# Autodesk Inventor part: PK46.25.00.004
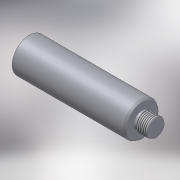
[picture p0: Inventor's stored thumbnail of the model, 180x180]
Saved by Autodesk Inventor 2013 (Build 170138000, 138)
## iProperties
Created: 2005-05
Part Number: PK46.25.00.004
Material: Steel, Mild
Document SubType Name: Modeling
Designer: PVitaliy
Manufacturer: Standard
Standards Organization: Custom
Density: 7.86 g/cm^3
Author: PVitaliy
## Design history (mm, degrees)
sketch "Эскиз2"
  geometry: L1 (0, 0)-(95.139, 0); L2 (0, 0)-(0, 25.897); L3 (0, 25.897)-(13, 35); L4 (13, 35)-(15, 35); L5 (15, 35)-(15, 50); L6 (15, 50)-(339, 50); L7 (339, 50)-(345, 46.536); L8 (345, 46.536)-(345, 24.5); L9 (345, 24.5)-(351, 24.5); L10 (351, 24.5)-(352.5, 26); L11 (352.5, 26)-(385, 26); L12 (385, 26)-(385, 0); L13 (385, 0)-(0, 0)
  constraints: 26 end point, 6 horizontal, 4 vertical, 1 other
  dimensions: "d0" = 70 diameter of L4 L1; "d1" = 35 deg angle of L3 L4; "d2" = 15 distance between parallel lines of L5 L2; "d3" = 2 distance of L3.end L4.end; "d4" = 100 diameter of L6 L1; "d5" = 330 distance between parallel lines of L8 L5; "d6" = 30 deg angle of L6 L7; "d7" = 6 horizontal distance of L6.end L7.end; "d8" = 385 distance between parallel lines of L12 L2; "d9" = 52 diameter of L11 L1; "d10" = 6 distance of L8.end L9.end; "d11" = 49 diameter of L9 L1; "d12" = 45 deg angle of L10 L9
revolve "Вращение1" sketch "Эскиз2" stored, may be unused: angle "d13" = 90 deg
feature "Резьба1" dims "d14" = 10, "d15" = 0
chamfer "Фаска1" distance "d16" = 1.6; stored, may be unused: second distance "d17" = 2, angle "d18" = 45 deg
fillet "Сопряжение1" dims "d19" = 1, "d20" = 0.5
body "Solid1"
